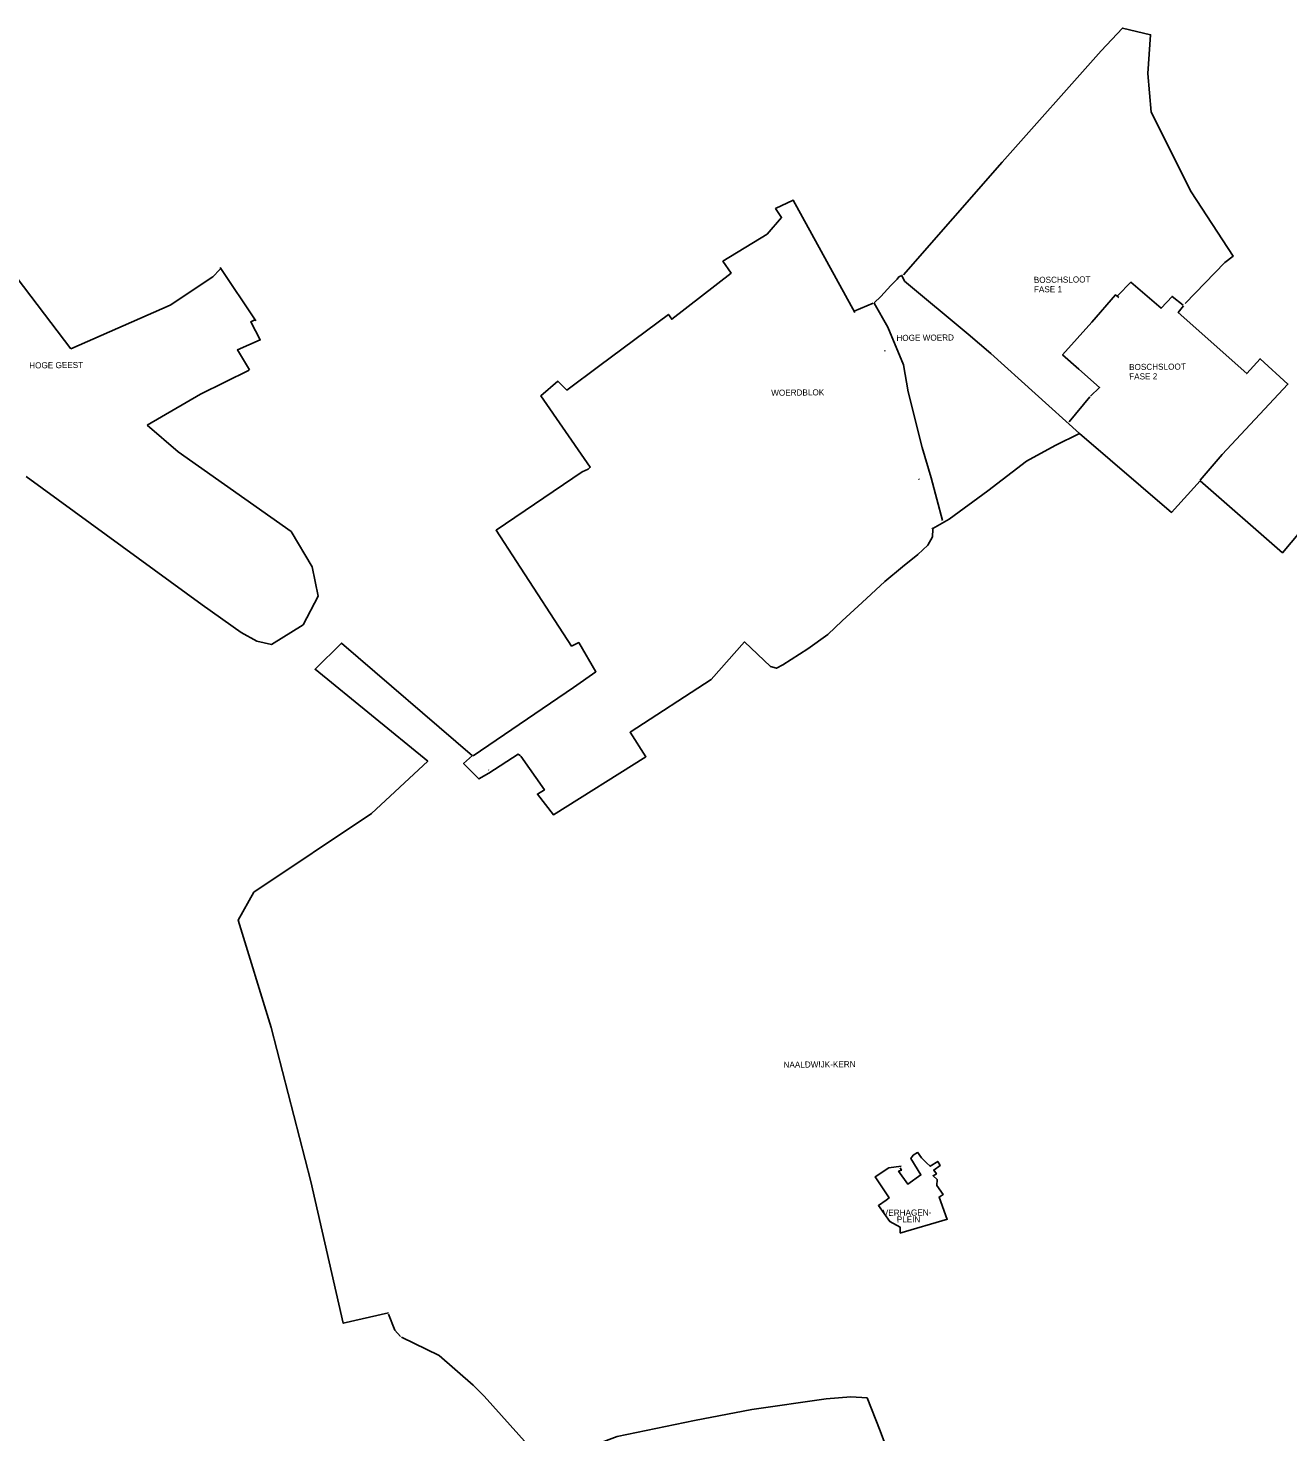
# Model space of a CAD drawing. Extents: x 69068 to 80855, y 440023 to 451362.
# Drawn here: x 72673 to 74532, y 445078 to 447150 of the extents above; entities that cross this region are included whole.
import ezdxf

# ---------------------------------------------------------------- set-up
doc = ezdxf.new("R2010")
doc.units = 0
doc.layers.add('Bemalingsgebiedsgrens', color=7, linetype='Continuous')
doc.layers.add('RIO_Leidingen', color=7, linetype='Continuous')

msp = doc.modelspace()

# ---------------------------------------------------------------- linework, layer by layer
at = {"layer": 'Bemalingsgebiedsgrens'}
for p, q in [((72736.1, 446676.4), (72539.7, 446933.6)), ((72944.7, 446782.1), (72957.1, 446794.6)), ((72956.7, 446796.5), (73008.9, 446718.1)), ((72945.4, 446783.1), (72882.8, 446741.1)), ((72882.8, 446741.1), (72736.1, 446676.4)), ((73892.3, 446732), (73920.3, 446744)), ((72927.6, 446609.9), (72999.2, 446645.3)), ((72848.5, 446564), (72927.6, 446609.9)), ((74240.1, 446605.6), (74209.3, 446569.1)), ((72894.4, 446524.5), (72848.5, 446564)), ((73061.4, 446407.1), (72894.4, 446524.5)), ((72670.4, 446488.2), (72930.1, 446298.7)), ((73092, 446354.9), (73061.4, 446407.1)), ((73100.9, 446311.5), (73092, 446354.9)), ((73079.2, 446269.4), (73100.9, 446311.5)), ((72930.1, 446298.7), (72987.5, 446257.9)), ((72987.5, 446257.9), (73010.4, 446245.2)), ((73032.1, 446240.1), (73079.2, 446269.4)), ((73010.4, 446245.2), (73032.1, 446240.1)), ((73959.7, 445371.5), (74030, 445392.4))]:
    msp.add_line(p, q, dxfattribs=at)
for points in [[(73964.9, 446785.9), (74110.5, 446952.2), (74256.5, 447116.2), (74288, 447150), (74329.5, 447140.1), (74325.7, 447083.1), (74330.6, 447026), (74389.6, 446908.3), (74451.5, 446813.6), (74439.1, 446804), (74380.8, 446743.6)], [(73893.1, 446730.4), (73802.1, 446896), (73776.1, 446883.5), (73785.1, 446870.5), (73763.6, 446845.9), (73698.5, 446805.9), (73710.5, 446788.4), (73623, 446720.4), (73618, 446727.4), (73516.9, 446651.8), (73467.9, 446615.8), (73454.8, 446628.8), (73429.8, 446607.3), (73497.9, 446508.6), (73502.6, 446501.9), (73499.8, 446499.1), (73490.6, 446495.3), (73363.7, 446408.9), (73393.6, 446362.6), (73475.1, 446238), (73485.6, 446243), (73511.1, 446200), (73478.1, 446177), (73330, 446075.9)], [(74006.8, 446411.9), (74008.3, 446411.3), (74032.3, 446425.2), (74089.3, 446467), (74146.5, 446510.7), (74188.7, 446533.8), (74224.9, 446551.9), (74093.6, 446669.9), (74060.2, 446698.3), (73966.5, 446776.7), (73962.7, 446784.9), (73958.2, 446782.7), (73955.4, 446779.5), (73946.2, 446770.2), (73931.5, 446754), (73921.6, 446744.3)], [(74281.4, 446755.5), (74300.6, 446775), (74345, 446736.6), (74361.2, 446754), (74377.8, 446741.2)], [(74282.5, 446752.4), (74277.7, 446756.3), (74243, 446715.9), (74199.6, 446667.8), (74223.8, 446646.8), (74254.4, 446619.8), (74240.7, 446606.8)], [(74022.6, 446423.1), (74005.9, 446486.4), (73992.6, 446531), (73971.6, 446613), (73964.8, 446652.8), (73941.6, 446708.8), (73921.5, 446743.9)], [(74378.1, 446740.2), (74370.3, 446730.2), (74471.4, 446640.2), (74491.1, 446661.9), (74532.2, 446624.7), (74435.3, 446520.6), (74402.6, 446482.6)], [(73000, 446645.7), (72982, 446675), (73015.5, 446689.9), (73001.6, 446716.7), (73007.7, 446719.2)], [(73937.2, 446674), (73937.5, 446673)], [(74665.4, 446544), (74524.1, 446375.8), (74402.6, 446481.8), (74360.6, 446435.1), (74224.9, 446551.9)], [(73987.6, 446485), (73987.8, 446483.9)], [(74008.2, 446410.3), (74007.5, 446399.3), (74000.9, 446387), (73985.9, 446373), (73963.2, 446354.9), (73937.5, 446333.3), (73903.7, 446302.3), (73874.6, 446275.3), (73853.1, 446254.9), (73823.6, 446233.7), (73787, 446210.4), (73777.3, 446205.2), (73768.8, 446207.9), (73730.3, 446244), (73681.3, 446188.5), (73561.3, 446110.7), (73584.9, 446074.6), (73448.6, 445988.9), (73424.7, 446019.5), (73435, 446025.6), (73400.2, 446075.6)], [(73204.8, 445253.8), (73138, 445238.5), (73090.2, 445448), (73031.7, 445675.1), (72983, 445833.4), (73006.1, 445874.6), (73179.8, 445990.9), (73262.7, 446068.1), (73096.6, 446203.7), (73135.7, 446242.3), (73328.8, 446075.8)], [(73329.1, 446076.4), (73315.7, 446064.5), (73338.3, 446041.9), (73352.8, 446050.6), (73396.1, 446078.2), (73399.9, 446076.2)], [(73352.7, 446055.2), (73353, 446055)], [(73959.8, 445468), (73961.9, 445464.4), (73957.6, 445462.9), (73971.3, 445443.9), (73990.6, 445457.4), (73975.7, 445481.5), (73979, 445486.6), (73985.6, 445490.6)], [(73985.5, 445491.2), (73991.5, 445482.8), (73998.7, 445475.3), (74004.1, 445470.2), (74015.4, 445477.4), (74018.8, 445471.2), (74009.5, 445464.5), (74013.6, 445458.9), (74008.5, 445456.3), (74014.4, 445450.9), (74013.9, 445442.1), (74023.6, 445428.8), (74017.5, 445424.7), (74029.6, 445391.7)], [(73961.5, 445470.5), (73943.5, 445467.9), (73923.2, 445454.7), (73943.7, 445423.6), (73939.1, 445420.3), (73927.8, 445412.3), (73944.7, 445388.6), (73960, 445380.5), (73960, 445371.8)], [(73204.8, 445251.9), (73214, 445228.5), (73222.4, 445218.9)], [(73224, 445218.2), (73279.7, 445190.9), (73329.8, 445147.4), (73346, 445131.2), (73461.4, 445002.7), (73473.3, 445029.5), (73515, 445061.1), (73542.5, 445071.5), (73656.6, 445094.9), (73741.3, 445111.4), (73850.7, 445127.1), (73887.4, 445129.8), (73911.1, 445128.5), (73930.7, 445079.6), (73955.7, 445012.2), (73959.1, 445001.1), (73968.8, 444966.4), (73995.6, 444971.4)]]:
    msp.add_lwpolyline(points, dxfattribs=at)

# ---------------------------------------------------------------- texts
at = {"layer": 'RIO_Leidingen'}
for s, p in [('BOSCHSLOOT', (74157.3, 446773.9)), ('FASE 1', (74157.4, 446759.9)), ('HOGE WOERD', (73954.5, 446688.2)), ('HOGE GEEST', (72674.7, 446647.7)), ('BOSCHSLOOT', (74297.9, 446645.3)), ('FASE 2', (74298, 446631.3)), ('WOERDBLOK', (73769.7, 446607.3)), ('NAALDWIJK-KERN', (73787.9, 445615.6)), ('VERHAGEN-', (73934.5, 445397)), ('PLEIN', (73955.1, 445387.2))]:
    msp.add_text(s, height=9, rotation=0.5, dxfattribs=at).set_placement(p)

doc.saveas('drawing.dxf')
